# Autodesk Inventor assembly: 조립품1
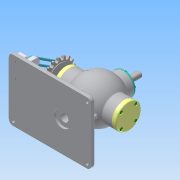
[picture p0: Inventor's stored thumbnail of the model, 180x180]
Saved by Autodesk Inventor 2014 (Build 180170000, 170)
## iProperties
Created: 2017-07
Part Number: 조립품1
Document SubType Name: Assembly
Designer: user
Mass: 2044.45 g
Surface Area: 2432.28 cm^2
Volume: 943.617 cm^3
Density: 2.16661 g/cm^3
Author: user
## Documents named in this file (20)
- C:\Users\user\Desktop\370707V1021\조립품1.iam
- C:\Users\user\Desktop\370707V1021\370707V1021\본체.ipt
- C:\Users\user\Desktop\370707V1021\370707V1021\고정핀.ipt
- C:\Users\user\Desktop\370707V1021\370707V1021\너트 M8x1.ipt
- C:\Users\user\Desktop\370707V1021\370707V1021\둥근머리 볼트 M4x8.ipt
- C:\Users\user\Desktop\370707V1021\370707V1021\뒤커버.ipt
- C:\Users\user\Desktop\370707V1021\370707V1021\베어링 6202.ipt
- C:\Users\user\Desktop\370707V1021\370707V1021\본체커버.ipt
- C:\Users\user\Desktop\370707V1021\370707V1021\볼트 M4x12.ipt
- C:\Users\user\Desktop\370707V1021\370707V1021\스프로킷.ipt
- C:\Users\user\Desktop\370707V1021\370707V1021\슬라이드 커버.ipt
- C:\Users\user\Desktop\370707V1021\370707V1021\슬라이드.ipt
- C:\Users\user\Desktop\370707V1021\370707V1021\앞커버.ipt
- C:\Users\user\Desktop\370707V1021\370707V1021\연결대.ipt
- C:\Users\user\Desktop\370707V1021\370707V1021\오일실.ipt
- C:\Users\user\Desktop\370707V1021\370707V1021\와셔 8x17.ipt
- C:\Users\user\Desktop\370707V1021\370707V1021\와셔 ISO 7093 A.ipt
- C:\Users\user\Desktop\370707V1021\370707V1021\축.ipt
- C:\Users\user\Desktop\370707V1021\370707V1021\키 3 x 3 x 12.ipt
- C:\Users\user\Desktop\370707V1021\스프링.ipt
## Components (1 placed, 1 different names)
1. 고정핀:1
